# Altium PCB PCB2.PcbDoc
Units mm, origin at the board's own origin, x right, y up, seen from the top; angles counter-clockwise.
Board outline 100 x 100 mm, 2 copper layers (Top Layer, Bottom Layer); 6 components, 7 nets, 41 pads, 2 vias.
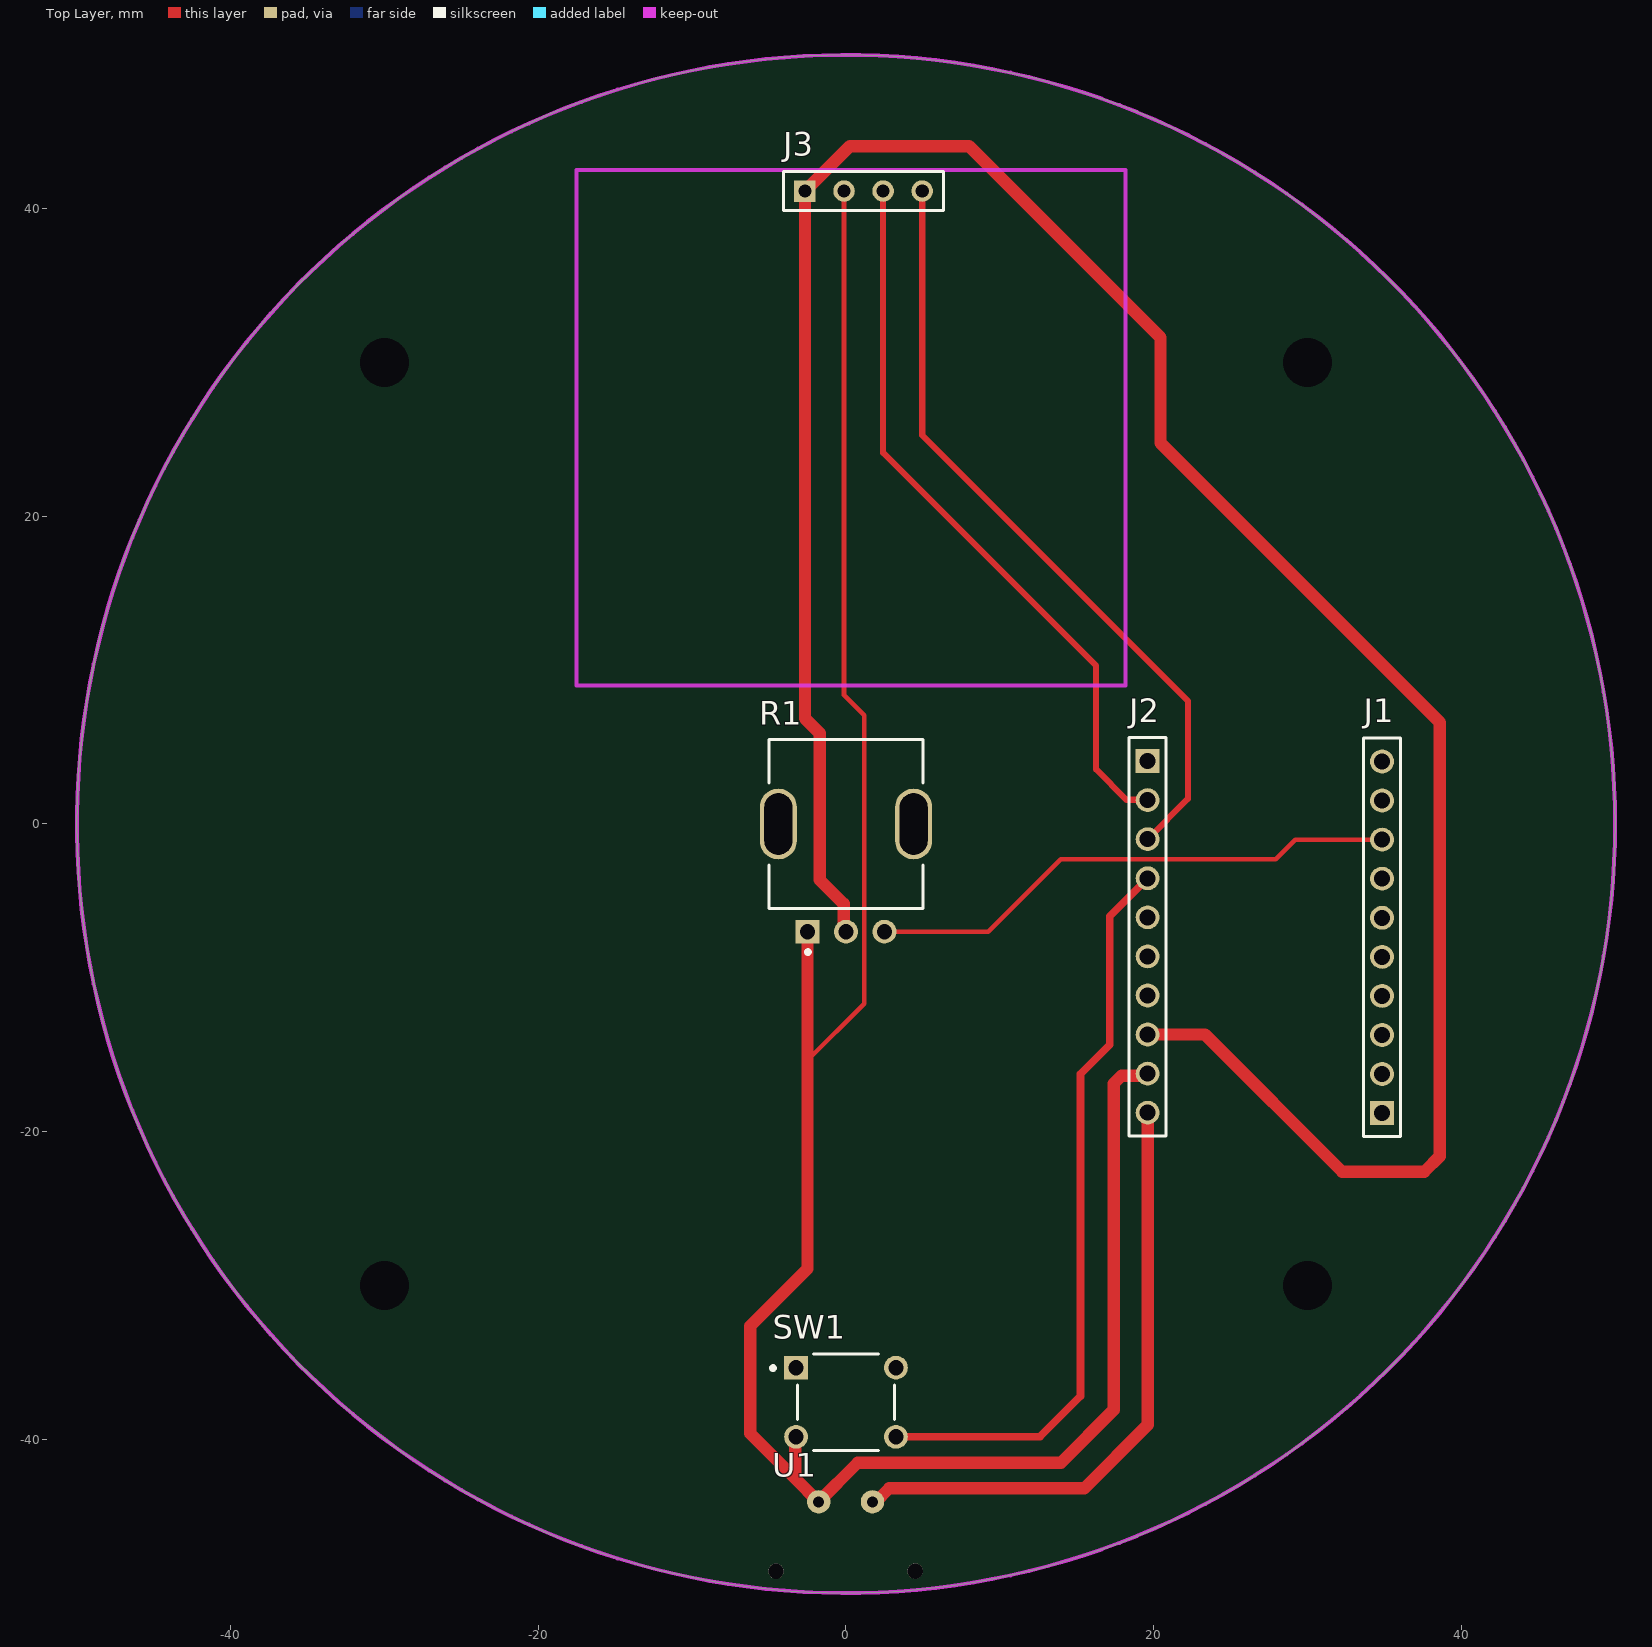
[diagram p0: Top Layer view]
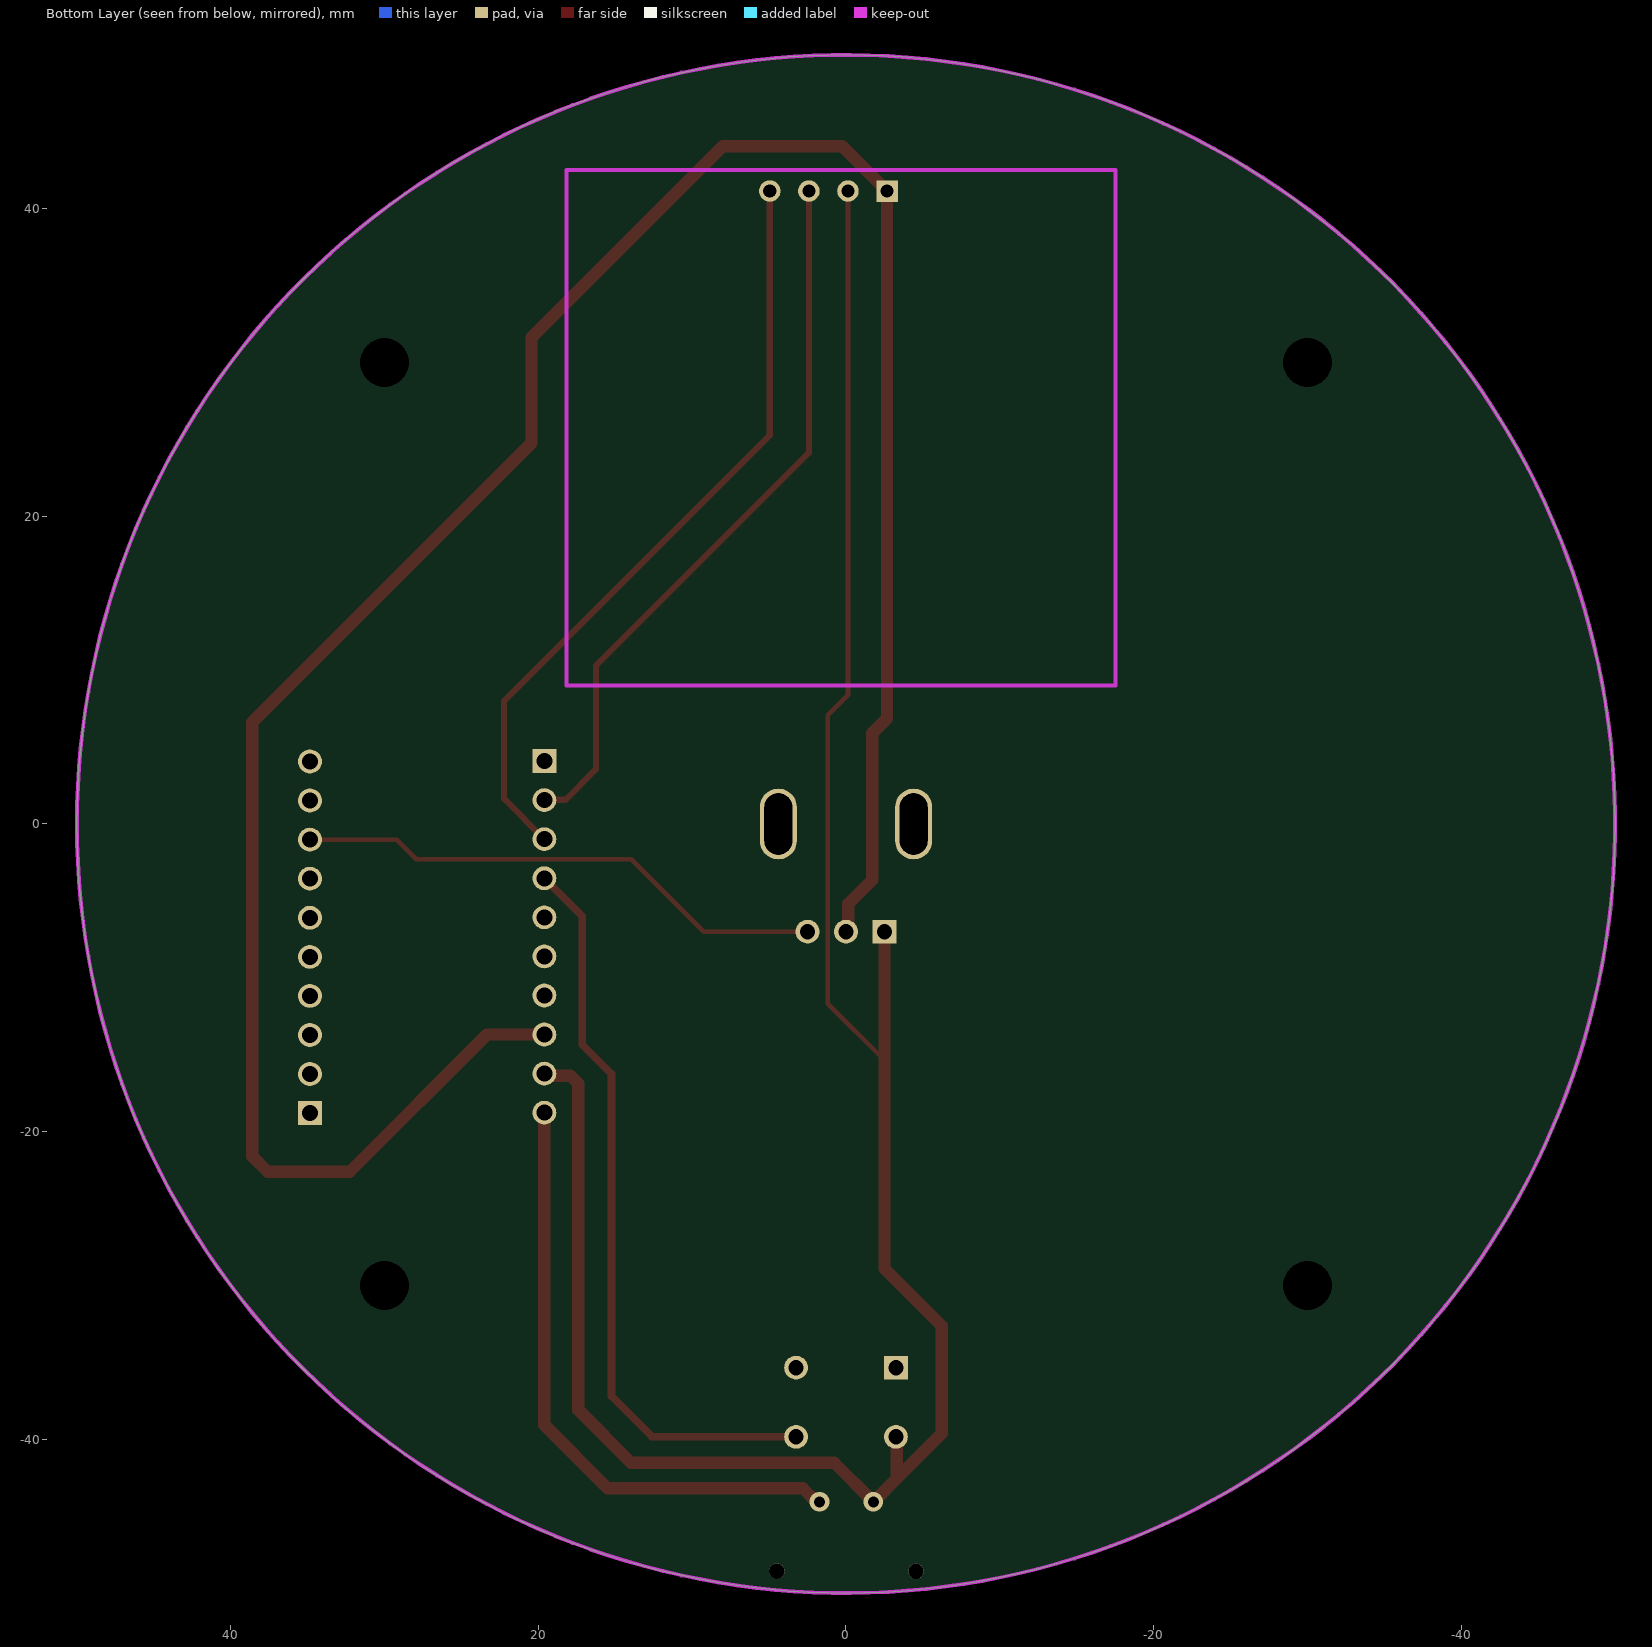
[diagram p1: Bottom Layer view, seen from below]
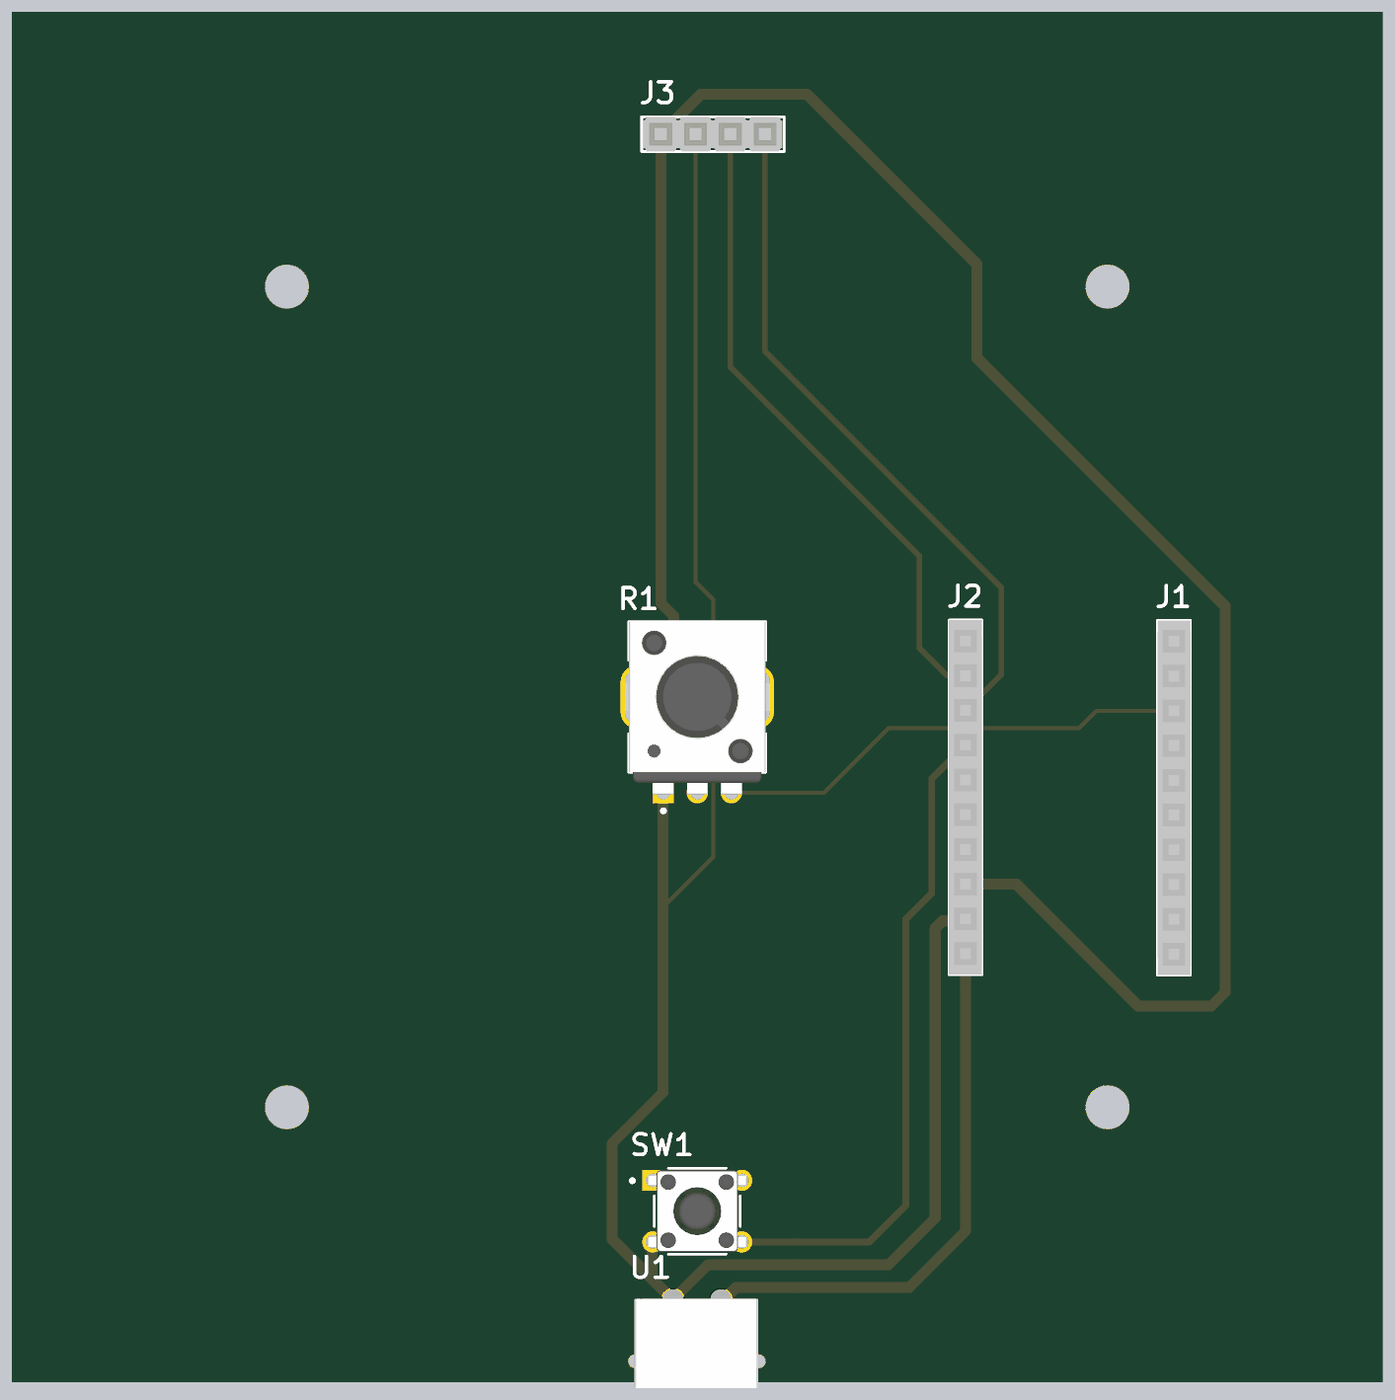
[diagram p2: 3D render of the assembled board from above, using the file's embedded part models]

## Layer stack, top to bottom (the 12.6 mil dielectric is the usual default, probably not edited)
Top Solder: solder mask 0.0102, Solder Resist, Dk 3.5
Top Layer: signal copper 0.0356
Dielectric 1: dielectric 0.32, FR-4, Dk 4.8
Bottom Layer: signal copper 0.0356
Bottom Solder: solder mask 0.0102, Solder Resist, Dk 3.5

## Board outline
-50,0 ccw(c0,0) 0,-50 ccw(c0,0) 50,0 ccw(c0,0) 0,50 ccw(c0,0)

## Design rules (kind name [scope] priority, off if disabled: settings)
Clearance [All] p1: gap=0.254 ignorepadtopadclearanceinfootprint=FALSE
PolygonConnect [All] p1: connectstyle=Relief reliefconductorwidth=0.254 reliefentries=4 polygonreliefangle="90 Angle" airgapwidth=0.254
RoutingVias [All] p1: holewidth=0.711 width=1.27 viastyle="Through Hole" minholewidth=0.711 minwidth=1.27 maxholewidth=0.711 maxwidth=1.27
SolderMaskExpansion [All] p1: expansion=0.102 istentingtop=FALSE
SupplyNets "Schematic Supply Nets_2" [InNet('+5')] p1: voltage=0.000
SupplyNets "Schematic Supply Nets_1" [InNet('+3v3')] p2: voltage=0.000
SupplyNets "Schematic Supply Nets" [InNet('GND')] p3: voltage=0.000
Width [All] p1: maxlimit=0.8 minlimit=0.254 preferedwidth=0.254
30 further rules are at their usual default settings.

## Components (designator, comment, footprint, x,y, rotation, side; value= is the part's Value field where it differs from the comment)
J1 "SSW-110-03-G-S" SMTC-SSW-110-03-X-S 34.85,-18.796 r90 top locked
J2 "SSW-110-03-G-S" SMTC-SSW-110-03-X-S 19.61,4.093 r270 top locked
J3 "SLW-104-01-G-S" SMTC-SLW-104-01-X-S -2.667,41.148 r0 top locked
R1 "PTV09A-4225F-B102" FP-PTV09A-4-MFG 0,0 r0 top locked
SW1 "3-1825910-1" FP-3-1825910-1-MFG 0,-37.592 r0 top locked
U1 "USB Type C 2 Pin Connector" "USB C Power Connector" 4.497,-50.569 r90 top locked

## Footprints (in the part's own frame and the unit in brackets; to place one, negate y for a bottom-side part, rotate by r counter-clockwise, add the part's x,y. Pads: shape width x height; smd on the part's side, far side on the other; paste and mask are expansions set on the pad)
FP-3-1825910-1-MFG [mm]
  rect 1.54x1.54 hole 0.99 paste-2539.97 mask+0: 1(-3.25,2.25)
  round 1.54 hole 0.99 paste-2539.97 mask+0: 2(3.25,2.25) 3(-3.25,-2.25) 4(3.25,-2.25)
  silkscreen extent -4.87,-3.15 3.15,3.15, body extent -4.12,-3.24 4.12,3.24, height 0.25
FP-PTV09A-4-MFG [mm]
  rect 1.55x1.55 hole 1 paste-2539.97 mask+0: 1(-2.5,-7)
  round 1.55 hole 1 paste-2539.97 mask+0: 2(0,-7) 3(2.5,-7)
  rrect100% 2.4x4.6 hole 4 slot 1.8 at 0 deg paste-2539.97 mask+0: 4(-4.4,0) 5(4.4,0)
  silkscreen extent -5,-8.45 5,5.5, body extent -5.8,-7.88 5.8,5.6, height 0.25
SMTC-SLW-104-01-X-S [mm] "Low Profile Socket Strip, 1x4 Pins, Vertical, 2.54mm Pitch, Female"
  rect 1.4x1.4 hole 0.86: 1(0,0)
  round 1.4 hole 0.86: 2(2.54,0) 3(5.08,0) 4(7.62,0)
  silkscreen extent -1.4,-1.27 9.02,1.27, body extent -1.27,-1.27 8.89,1.27, height 4.57
SMTC-SSW-110-03-X-S [mm] "SQ Post Socket, 1x10 Pins, Vertical, 2.54mm Pitch, Female"
  rect 1.55x1.55 hole 1.04: 1(0,0)
  round 1.55 hole 1.04: 2(2.54,0) 3(5.08,0) 4(7.62,0) 5(10.16,0) 6(12.7,0) 7(15.24,0) 8(17.78,0) 9(20.32,0) 10(22.86,0)
  silkscreen extent -1.53,-1.2 24.39,1.2, body extent -1.52,-1.21 24.38,1.21, height 8.51
"USB C Power Connector" [mm]
  round 1.524 smd: GND(6.5,6.275) VCC(6.5,2.775)
  round 1 hole 1 paste-2539.97 mask+0: NC(2,9.05)
  round 1 hole 1 mask+0: NC(2,0)
  body extent 0.05,0.05 6.55,9.1, height 3

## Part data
J1 J2: library part CMP-1023-00394-1, "SQ Post Socket, Through-hole, Vertical, -55 to 125 degC, 2.54 mm Pitch, 10-Pin, Female, RoHS", Manufacturer=Samtec, Temperature Range="-55 to 125 degC"
J3: library part CMP-1023-00130-1, "Low Profile Socket Strips, Through-hole, Vertical, -55 to 125 degC, 2.54 mm Pitch, 4-Pin, Female, RoHS", Manufacturer=Samtec, Temperature Range="-55 to 125 degC"
R1: library part CMP-07234-000055-1, "POT 1K OHM 1/20W CARBON LINEAR", Max Operating Temperature=50°C, Max Power Dissipation=50mW, Min Operating Temperature=-10°C, Package Quantity=100, Resistance=1kR, Resistance Tolerance=20%, Resistor Type=Carbon
SW1: library part CMP-03407-000001-1, "SWITCH TACTILE SPST-NO 0.05A 24V", Contact Current Rating=50mA, Contact Resistance=100mΩ, Manufacturer="TE Connectivity", Operating Force=160gf, Package=0, Temperature="-35°C to +85°C", Temperature Range High=+85°C, Temperature Range Low=-35°C

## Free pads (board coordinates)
  round 1.524 hole 3.2: 13(30,30) 14(-30,-30) 15(-30,30) 16(30,-30)

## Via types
v1: diameter 1.27, hole 0.711, Top Layer to Bottom Layer, 2 vias

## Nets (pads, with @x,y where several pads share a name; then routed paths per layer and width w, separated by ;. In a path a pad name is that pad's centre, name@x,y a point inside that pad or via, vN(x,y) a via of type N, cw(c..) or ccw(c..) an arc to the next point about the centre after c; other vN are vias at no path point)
+3v3: J2.8 J3.1 R1.2 | length 162.6
  Top Layer w0.8: R1.2 -0.144,-6.856 -0.144,-5.19 -1.714,-3.619 -1.714,5.905 -2.667,6.858 J3.1 0.254,44.069 8.001,44.069 20.447,31.623 20.447,24.765 38.608,6.604 38.608,-21.59 37.592,-22.606 32.258,-22.606 23.339,-13.687 J2.8
+5: J2.10 U1.VCC | length 40.3
  Top Layer w0.8: v1(1.722,-44.069) 1.918,-44.069 2.807,-43.18 15.494,-43.18 19.61,-39.064 J2.10
GND: J2.9 J3.2 R1.1 SW1.3 U1.GND | length 147.1
  Top Layer w0.3: -2.5,-15.367 1.179,-11.688 1.179,7.076 -0.127,8.382 J3.2
  Top Layer w0.8: SW1.3 -3.302,-39.894 -3.302,-42.545 ; R1.1 -2.5,-15.367 -2.5,-28.916 -6.223,-32.639 -6.223,-39.624 -3.302,-42.545 ; J2.9 19.466,-16.371 17.919,-16.371 17.399,-16.891 17.399,-38.1 13.976,-41.523 0.768,-41.523 v1(-1.778,-44.069) -3.302,-42.545
POTI: J1.8 R1.3 | length 34.8
  Top Layer w0.3: R1.3 9.256,-7 13.97,-2.286 27.94,-2.286 29.21,-1.016 J1.8
SCK: J2.2 J3.3 | length 47.5
  Top Layer w0.4: J3.3 2.413,24.13 16.256,10.287 16.256,3.556 18.235,1.577 19.586,1.577 J2.2
SDA: J2.3 J3.4 | length 50.4
  Top Layer w0.4: J3.4 4.953,25.273 22.225,8.001 22.225,1.628 J2.3
SW: J2.4 SW1.4 | length 48.6
  Top Layer w0.5: SW1.4 12.609,-39.842 15.24,-37.211 15.24,-16.256 17.145,-14.351 17.145,-5.992 J2.4
pads on no net: J1.1 J1.2 J1.3 J1.4 J1.5 J1.6 J1.7 J1.9 J1.10 J2.1 J2.5 J2.6 J2.7 R1.4 R1.5 SW1.1 SW1.2 U1.NC

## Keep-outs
Keep-Out Layer:
  circle w0.254: c0,0 r50
  lines w0.254: -17.526,9.017 18.174,9.017 18.174,42.517 -17.526,42.517 -17.526,9.017

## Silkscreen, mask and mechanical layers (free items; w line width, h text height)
PCBBorder:
  the board outline again, w0.2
